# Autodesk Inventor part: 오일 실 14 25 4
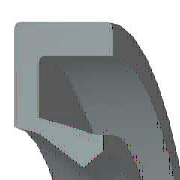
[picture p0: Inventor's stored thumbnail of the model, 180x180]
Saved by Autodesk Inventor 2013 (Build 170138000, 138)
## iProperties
Created: 2012-02
Part Number: 오일 실 14 25 4
Material: 고무
Description: 오일 실 - 스프링 장착, 비스프링, 고무 덮개 G
Document SubType Name: Modeling
Standard: JIS B 2402
Designer: mdu-01
Standards Organization: JIS
Language: ko-KR
Size Designation: 14 25 4 A
Categories: <MemberInstance><Categories><Category DisplayName="샤프트 부품" InternalName="7f7aeb1f-a693-4053-b835-cee3144e0d98" Mnemonic="SHFT"><Category DisplayName="실링" Intern
Density: 0.93 g/cm^3
IsCustomPart: 1
Author: mdu-01
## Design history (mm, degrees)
body "Solid1"
revolve "회전1" stored, may be unused: angle "d29" = 360 deg
chamfer "모따기1" distance "d30" = 0.2 (= 0.05 x b); stored, may be unused: second distance "d31" = 0.4 (= 0.1 x b), angle "d39" = 45 deg
chamfer "모따기2" distance "d32" = 0.4 (= 0.1 x b); stored, may be unused: second distance "d33" = 0.2 (= 0.05 x b), angle "d40" = 45 deg
fillet "모깎기1" dims "d34" = 0.2 (= 0.05 x b)
sketch "스케치2"
  geometry: L1 (7.914, -2.75)-(8.189, -4); L2 (7.547, -2.626)-(7.914, -2.75); L3 (7, -1.376)-(7.547, -2.626); L4 (8, -0.976)-(7, -1.376); L5 (8.956, -3)-(8, -0.976); L6 (10.056, -3)-(8.956, -3); L7 (11.278, -1)-(10.056, -3); L8 (11.278, 0)-(11.278, -1); L9 (12.5, 0)-(11.278, 0); L10 (12.5, -4)-(12.5, 0); L11 (8.189, -4)-(12.5, -4); L12 (0, -9.6)-(0, 1.6) reference; L13 (28, 0)-(14, 0) reference
  constraints: 22 end point, 3 horizontal, 2 vertical
  dimensions: "d2" = 4 distance of L10.start L9.start (= b); "d4" = 1 vertical distance of L5.start L1.end (= 0.25 x b); "d6" = 1.22222 distance of L9.start L8.start (= 0.111111 x dd - 0.111111 x Diam); "d8" = 1 distance of L8.start L7.start (= 0.25 x b); "d10" = 1.22222 horizontal distance of L7.start L6.start (= 0.111111 x dd - 0.111111 x Diam); "d12" = 0.97561 vertical distance of L9.start L4.start (= 0.243902 x b); "d14" = 1 horizontal distance of L4.start L3.start (= 0.0909091 x dd - 0.0909091 x Diam); "d16" = 0.4 vertical distance of L4.start L3.start (= 0.1 x b); "d18" = 1.1 distance of L6.start L5.start (= 0.1 x dd - 0.1 x Diam); "d20" = 1.25 vertical distance of L3.start L2.start (= 0.3125 x b); "d22" = 0.54726 horizontal distance of L3.start L2.start (= 0.0497512 x dd - 0.0497512 x Diam); "d24" = 0.275 horizontal distance of L1.start L1.end (= 0.025 x dd - 0.025 x Diam); "d26" = 1.25 vertical distance of L1.start L1.end (= 0.3125 x b); "d28" = 0.36667 horizontal distance of L2.start L1.start (= 0.0333333 x dd - 0.0333333 x Diam); "d35" = 0 distance between parallel lines of L13 L9; "d36" = 12.5 distance between parallel lines of L12 L10 (= 0.5 x dd); "d37" = 7 distance from line of L12 L3.start (= 0.5 x Diam)
other parameters: "dd" = 25 [user parameter; used in 8 equation terms], "Diam" = 14 [user parameter; used in 8 equation terms], "b" = 4 [user parameter; used in 12 equation terms], "d1" = 8 (derived), "d3" = 2 (derived), "d5" = 2.22222 (derived), "d7" = 2 (derived), "d9" = 2.22222 (derived), "d11" = 1.95122 (derived), "d13" = 1.81818 (derived), "d15" = 0.8 (derived), "d17" = 2 (derived), "d19" = 2.5 (derived), "d21" = 0.99502 (derived), "d23" = 0.5 (derived), "d25" = 2.5 (derived), "d27" = 0.66667 (derived), "d38" = 0
